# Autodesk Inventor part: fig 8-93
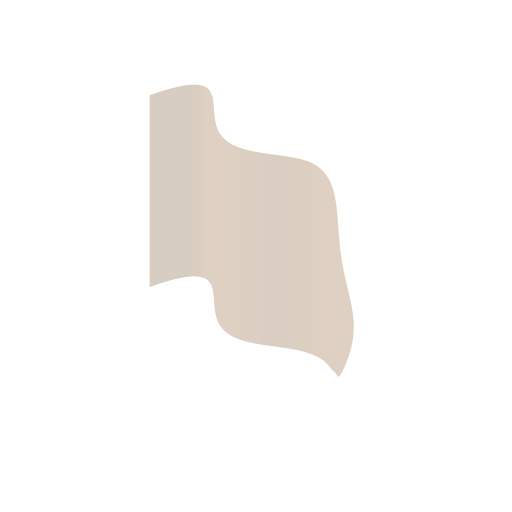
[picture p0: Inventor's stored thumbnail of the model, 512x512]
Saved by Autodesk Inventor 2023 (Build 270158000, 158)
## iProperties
Part Number: fig 8-93
Document SubType Name: Modeling
Created: 2003-08
Designer: Owner
Manufacturer: Standard
Standards Organization: Custom
Density: 1 g/cm^3
Material: Generic
Appearance: Default
Control State: 0
Master: False
Checked Out: False
Shininess: 64.0
Length Units: 11269
Angle Units: 11279
Time Units: 11290
Mass Units: 11283
Length Display Precision: 3
Angle Display Precision: 2
Compacted: True
Density: 0.0
Volumn: 0.0
Area: 0.0
PropertySet Name: Model Information
Author: Owner
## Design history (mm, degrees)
sketch "Sketch1"
  geometry: 7 further points
  constraints: 7 other
  dimensions: "d0" = 80 horizontal distance of point (40, 1.742) point (-40, -4.065); "d1" = 40 horizontal distance of point (0, 0) point (-40, -4.065)
extrude_surface "ExtrusionSrf1" sketch "Sketch1" dims "d2" = 80, "d3" = 0
sketch "Sketch2"
  geometry: L1 (40, 0)-(40, -40) reference; L2 (-40, 0)-(-40, -40) reference; 7 further points
  constraints: 2 point on line, 7 other
extrude_surface "ExtrusionSrf2" sketch "Sketch2" dims "d4" = 80, "d5" = 0
workplane "Work Plane1"
sketch "Sketch4"
  geometry: L1 (70.027, 16.004)-(-4, 16.004); A1 r 29.004 centre (-4, -13) between (-4, 16.004) and (-2.981, -41.986)
  constraints: 2 end point, 2 point on circle, 1 centre point, 1 horizontal, 1 tangent
feature "Trim1" sketch "Sketch4"
body "Srf1"
body "Srf2"
other parameters: "d6" = -54.75
